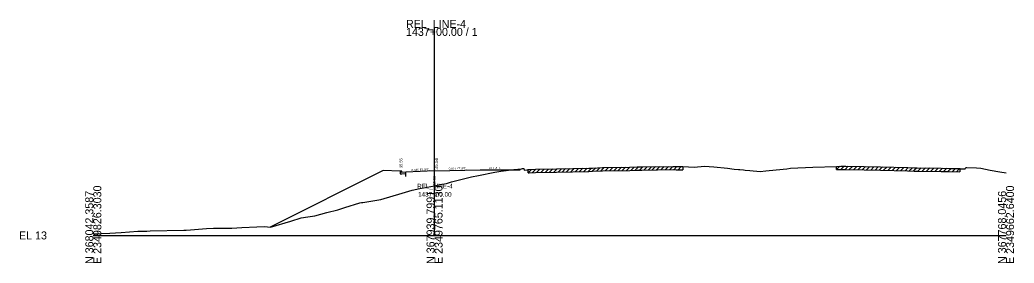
# Model space of a CAD drawing. Extents: x -26 to 2350146, y -10 to 368200.
# Drawn here: x 974.3 to 1322.3, y 8490.3 to 8575.4 of the extents above; entities that cross this region are included whole.
import ezdxf

# ---------------------------------------------------------------- set-up
doc = ezdxf.new("R2010")
doc.units = 0
for name, color, linetype in [('RD_GPK_XS_Cell', 7, 'Continuous'), ('RD_XS_CurbBase', 7, 'Continuous'), ('RD_XS_CurbFront', 7, 'Continuous'), ('RD_XS_CurbTop', 7, 'Continuous'), ('RD_XS_EarthShd', 7, 'Continuous'), ('RD_XS_ExGround', 7, 'Continuous'), ('RD_XS_ExPaveRet', 7, 'Continuous'), ('RD_XS_MatchLine', 7, 'Continuous'), ('RD_XS_Pave', 7, 'Continuous'), ('RD_XS_PaveShd', 7, 'Continuous'), ('RD_XS_TieSlope', 7, 'Continuous'), ('RD_XS_TX_Elev_EX', 7, 'Continuous'), ('RD_XS_TX_Elev_PR', 7, 'Continuous'), ('RD_XS_TX_Slope', 7, 'Continuous'), ('RD_XS_TX_Station', 7, 'Continuous'), ('RD_XS_TX_TOC', 7, 'Continuous')]:
    doc.layers.add(name, color=color, linetype=linetype)

msp = doc.modelspace()

# ---------------------------------------------------------------- linework, layer by layer
at = {"layer": 'RD_GPK_XS_Cell'}
for p, q in [((1119.43, 8500), (1119.43, 8572.65)), ((1000, 8500), (1119.43, 8500)), ((1119.43, 8500), (1319.43, 8500))]:
    msp.add_line(p, q, dxfattribs=at)
at = {"layer": 'RD_XS_CurbBase'}
for p, q in [((1107.43, 8522.55), (1107.43, 8521.55)), ((1107.43, 8521.55), (1107.93, 8521.55)), ((1107.93, 8521.55), (1109.43, 8521.64)), ((1109.43, 8520.57), (1109.43, 8521.64))]:
    msp.add_line(p, q, dxfattribs=at)
at = {"layer": 'RD_XS_CurbFront'}
msp.add_line((1109.43, 8521.64), (1109.43, 8522.14), dxfattribs=at)
at = {"layer": 'RD_XS_CurbTop'}
for p, q in [((1107.93, 8522.55), (1107.43, 8522.55)), ((1108.01, 8522.05), (1107.93, 8522.55)), ((1109.43, 8522.14), (1108.01, 8522.05)), ((1109.43, 8522.16), (1109.43, 8522.14))]:
    msp.add_line(p, q, dxfattribs=at)
at = {"layer": 'RD_XS_EarthShd'}
for p, q in [((1107.43, 8522.55), (1101.43, 8522.67)), ((1145.43, 8522.99), (1149.43, 8522.99))]:
    msp.add_line(p, q, dxfattribs=at)
at = {"layer": 'RD_XS_ExGround'}
msp.add_lwpolyline([(1000, 8500.52), (1005.78, 8500.8), (1009.77, 8500.98), (1015.62, 8501.54), (1018.73, 8501.51), (1019.85, 8501.63), (1031.68, 8501.81), (1032.55, 8501.81), (1034.02, 8501.91), (1039.62, 8502.47), (1042.02, 8502.54), (1046.53, 8502.52), (1048.44, 8502.5), (1052.03, 8502.83), (1057.26, 8503.06), (1059.94, 8503.14), (1062.04, 8502.89), (1069.19, 8505.03), (1072.76, 8506.21), (1075.09, 8506.48), (1077.55, 8506.85), (1081.7, 8507.97), (1085.56, 8508.94), (1088, 8509.77), (1093.32, 8511.38), (1093.91, 8511.5), (1094.29, 8511.57), (1099.93, 8512.47), (1100.59, 8512.63), (1108.15, 8514.8), (1111.59, 8515.8), (1114.31, 8516.39), (1119.43, 8517.39), (1121.4, 8517.77), (1123.61, 8518.19), (1125.32, 8518.72), (1132.42, 8520.52), (1134.82, 8521.02), (1140.55, 8522.15), (1142.65, 8522.5), (1147.21, 8523.02), (1149.86, 8523.35), (1150.24, 8523.39), (1150.67, 8523.37), (1150.83, 8522.88), (1151.88, 8522.94), (1152.15, 8523.05), (1152.53, 8523.07), (1154.76, 8523.15), (1162.14, 8523.3), (1173.47, 8523.55), (1174.69, 8523.6), (1178.24, 8523.72), (1187.77, 8523.92), (1190.35, 8523.97), (1191.92, 8523.99), (1202.94, 8524.16), (1203.97, 8524.14), (1206.34, 8524.11), (1210.33, 8523.93), (1213.96, 8524.22), (1217.23, 8523.99), (1221.98, 8523.5), (1224.29, 8523.23), (1225.77, 8523.09), (1226.26, 8523.05), (1227.6, 8522.92), (1228.11, 8522.88), (1229.74, 8522.71), (1233.39, 8522.33), (1235.43, 8522.56), (1238.99, 8522.97), (1242.69, 8523.36), (1244.02, 8523.5), (1251.82, 8523.87), (1260.09, 8524.18), (1261.65, 8524.2), (1263.39, 8524.21), (1269.77, 8524.09), (1275.47, 8523.98), (1284.95, 8523.75), (1287.23, 8523.7), (1288.34, 8523.68), (1296.76, 8523.56), (1299.58, 8523.48), (1303.27, 8523.37), (1303.47, 8523.3), (1304.74, 8523.28), (1305.18, 8523.26), (1305.36, 8523.73), (1305.74, 8523.73), (1309.12, 8523.61), (1310.61, 8523.6), (1313.93, 8522.88), (1317.21, 8522.26), (1319.43, 8521.91)], dxfattribs=at)
at = {"layer": 'RD_XS_ExPaveRet'}
for p, q in [((1152.15, 8521.9), (1153.34, 8523.1)), ((1152.15, 8521.9), (1152.15, 8523.05)), ((1152.15, 8521.9), (1152.53, 8521.93)), ((1152.53, 8521.93), (1154.76, 8522)), ((1153.65, 8521.96), (1154.83, 8523.15)), ((1154.76, 8522), (1162.14, 8522.16)), ((1155.15, 8522.01), (1156.31, 8523.18)), ((1156.65, 8522.04), (1157.81, 8523.21)), ((1158.15, 8522.07), (1159.31, 8523.24)), ((1159.65, 8522.1), (1160.81, 8523.27)), ((1161.15, 8522.14), (1162.31, 8523.3)), ((1162.14, 8522.16), (1173.47, 8522.41)), ((1162.65, 8522.17), (1163.81, 8523.34)), ((1164.15, 8522.2), (1165.31, 8523.37)), ((1165.65, 8522.23), (1166.81, 8523.4)), ((1167.15, 8522.27), (1168.31, 8523.44)), ((1168.65, 8522.3), (1169.81, 8523.47)), ((1170.15, 8522.33), (1171.31, 8523.5)), ((1171.65, 8522.37), (1172.81, 8523.54)), ((1173.15, 8522.4), (1174.33, 8523.58)), ((1173.47, 8522.41), (1174.69, 8522.45)), ((1174.65, 8522.45), (1175.83, 8523.64)), ((1174.69, 8522.45), (1178.24, 8522.58)), ((1176.15, 8522.51), (1177.33, 8523.69)), ((1177.65, 8522.56), (1178.82, 8523.74)), ((1178.24, 8522.58), (1187.77, 8522.78)), ((1179.15, 8522.6), (1180.31, 8523.77)), ((1180.65, 8522.63), (1181.81, 8523.8)), ((1182.15, 8522.66), (1183.31, 8523.83)), ((1183.65, 8522.69), (1184.81, 8523.86)), ((1185.15, 8522.72), (1186.31, 8523.89)), ((1186.65, 8522.75), (1187.81, 8523.92)), ((1187.77, 8522.78), (1190.35, 8522.83)), ((1188.15, 8522.78), (1189.31, 8523.95)), ((1189.65, 8522.81), (1190.81, 8523.98)), ((1190.35, 8522.83), (1191.92, 8522.85)), ((1191.15, 8522.84), (1192.31, 8524)), ((1191.92, 8522.85), (1202.94, 8523.02)), ((1192.65, 8522.86), (1193.81, 8524.02)), ((1194.15, 8522.88), (1195.31, 8524.05)), ((1195.65, 8522.91), (1196.81, 8524.07)), ((1197.15, 8522.93), (1198.31, 8524.09)), ((1198.65, 8522.95), (1199.81, 8524.11)), ((1200.15, 8522.97), (1201.31, 8524.14)), ((1201.65, 8523), (1202.81, 8524.16)), ((1202.94, 8523.02), (1203.97, 8523)), ((1203.15, 8523.01), (1204.27, 8524.14)), ((1203.97, 8523), (1206.34, 8522.96)), ((1204.65, 8522.99), (1205.77, 8524.12)), ((1206.34, 8524.11), (1206.34, 8522.96)), ((1260.09, 8523.04), (1261.24, 8524.19)), ((1260.09, 8523.04), (1260.09, 8524.18)), ((1260.09, 8523.04), (1261.65, 8523.05)), ((1261.59, 8523.05), (1262.74, 8524.2)), ((1261.65, 8523.05), (1263.39, 8523.06)), ((1263.09, 8523.06), (1264.22, 8524.19)), ((1263.39, 8523.06), (1269.77, 8522.95)), ((1264.59, 8523.04), (1265.71, 8524.16)), ((1266.09, 8523.01), (1267.21, 8524.14)), ((1267.59, 8522.99), (1268.71, 8524.11)), ((1269.09, 8522.96), (1270.21, 8524.08)), ((1269.77, 8522.95), (1275.47, 8522.83)), ((1270.59, 8522.93), (1271.71, 8524.05)), ((1272.09, 8522.9), (1273.21, 8524.02)), ((1273.59, 8522.87), (1274.71, 8523.99)), ((1275.09, 8522.84), (1276.21, 8523.96)), ((1275.47, 8522.83), (1284.95, 8522.61)), ((1276.59, 8522.81), (1277.71, 8523.92)), ((1278.09, 8522.77), (1279.21, 8523.89)), ((1279.59, 8522.74), (1280.71, 8523.85)), ((1281.09, 8522.7), (1282.21, 8523.82)), ((1282.59, 8522.67), (1283.71, 8523.78)), ((1284.09, 8522.63), (1285.21, 8523.75)), ((1284.95, 8522.61), (1287.23, 8522.55)), ((1285.59, 8522.59), (1286.71, 8523.71)), ((1287.09, 8522.56), (1288.21, 8523.68)), ((1287.23, 8522.55), (1288.34, 8522.54)), ((1288.34, 8522.54), (1296.76, 8522.41)), ((1288.59, 8522.53), (1289.72, 8523.66)), ((1290.09, 8522.51), (1291.22, 8523.64)), ((1291.59, 8522.49), (1292.72, 8523.62)), ((1293.09, 8522.47), (1294.22, 8523.59)), ((1294.59, 8522.45), (1295.72, 8523.57)), ((1296.09, 8522.42), (1297.21, 8523.54)), ((1296.76, 8522.41), (1299.58, 8522.34)), ((1297.59, 8522.39), (1298.7, 8523.5)), ((1299.09, 8522.35), (1300.2, 8523.46)), ((1299.58, 8522.34), (1303.27, 8522.23)), ((1300.59, 8522.31), (1301.7, 8523.42)), ((1302.09, 8522.27), (1303.2, 8523.38)), ((1303.27, 8523.37), (1303.27, 8522.23))]:
    msp.add_line(p, q, dxfattribs=at)
at = {"layer": 'RD_XS_MatchLine'}
msp.add_line((1149.43, 8522.99), (1149.43, 8523.3), dxfattribs=at)
at = {"layer": 'RD_XS_Pave'}
for q in [(1109.43, 8522.16), (1135.43, 8522.99)]:
    msp.add_line((1119.43, 8522.56), q, dxfattribs=at)
at = {"layer": 'RD_XS_PaveShd'}
msp.add_line((1135.43, 8522.99), (1145.43, 8522.99), dxfattribs=at)
at = {"layer": 'RD_XS_TieSlope'}
msp.add_line((1101.43, 8522.67), (1061.89, 8502.9), dxfattribs=at)

# ---------------------------------------------------------------- texts
at = {"layer": 'RD_GPK_XS_Cell'}
for s, p in [('REL_LINE-4', (1109.43, 8572.65)), ('1437+00.00 / 1', (1109.43, 8569.85)), ('EL 13', (974, 8498.6))]:
    msp.add_text(s, height=2.8, dxfattribs=at).set_placement(p)
for s, p in [('N 368042.3587', (1000, 8490)), ('E 2349826.3030', (1002.8, 8490)), ('N 367939.7991', (1119.43, 8490)), ('E 2349765.1130', (1122.23, 8490)), ('N 367768.0456', (1319.43, 8490)), ('E 2349662.6400', (1322.23, 8490))]:
    msp.add_text(s, height=2.8, rotation=90, dxfattribs=at).set_placement(p)
at = {"layer": 'RD_XS_TX_Elev_EX'}
msp.add_text('30.39', height=1, rotation=90, dxfattribs=at).set_placement((1119.93, 8517.39))
at = {"layer": 'RD_XS_TX_Elev_PR'}
for s, height, p in [('35.55', 1, (1108.18, 8523.55)), (' 35.56', 1.2, (1120.63, 8522.56))]:
    msp.add_text(s, height=height, rotation=90, dxfattribs=at).set_placement(p)
at = {"layer": 'RD_XS_TX_Slope'}
for s, rotation, p in [('0.040 FT./FT.', 2.2906, (1111.39, 8522.49)), ('0.027 FT./FT.', 1.5318, (1124.39, 8522.94))]:
    msp.add_text(s, height=0.75, rotation=rotation, dxfattribs=at).set_placement(p)
msp.add_text('0 FT./FT.', height=0.75, dxfattribs=at).set_placement((1138.39, 8523.24))
at = {"layer": 'RD_XS_TX_Station'}
for s, p in [('REL_LINE-4', (1113.36, 8516.46)), ('1437+00.00', (1113.66, 8513.56))]:
    msp.add_text(s, height=1.6, dxfattribs=at).set_placement(p)
at = {"layer": 'RD_XS_TX_TOC'}
msp.add_text('TOCLT', height=0.05, dxfattribs=at).set_placement((1107.98, 8522.5))

doc.saveas('drawing.dxf')
